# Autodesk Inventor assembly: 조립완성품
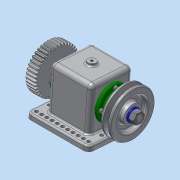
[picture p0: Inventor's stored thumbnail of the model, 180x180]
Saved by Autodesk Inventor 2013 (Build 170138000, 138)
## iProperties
Created: 2018-11
Part Number: 조립완성품
Document SubType Name: Assembly
Designer: dgall
Author: dgall
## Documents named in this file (13)
- C:\Users\dgall\Desktop\481107V1031\조립완성품.iam
- C:\Users\dgall\Desktop\481107V1031\축.ipt
- C:\Users\dgall\Desktop\481107V1031\베어링 6203.ipt
- C:\Users\dgall\Desktop\481107V1031\커버.ipt
- C:\Users\dgall\Desktop\481107V1031\오일 실 26 38 8.ipt
- C:\Users\dgall\Desktop\481107V1031\부시.ipt
- C:\Users\dgall\Desktop\481107V1031\키 5x5x12.ipt
- C:\Users\dgall\Desktop\481107V1031\스퍼기어.ipt
- C:\Users\dgall\Desktop\481107V1031\V벨트풀리.ipt
- C:\Users\dgall\Desktop\481107V1031\와셔 12x24.ipt
- C:\Users\dgall\Desktop\481107V1031\너트 M12x1.25.ipt
- C:\Users\dgall\Desktop\481107V1031\볼트 M4.ipt
- C:\Users\dgall\Desktop\481107V1031\본체도면.ipt
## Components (1 placed, 1 different names)
1. V벨트풀리:1 — 각도:4
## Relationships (1: Angle 1)
- 각도:4 [Angle]: V벨트풀리:1
